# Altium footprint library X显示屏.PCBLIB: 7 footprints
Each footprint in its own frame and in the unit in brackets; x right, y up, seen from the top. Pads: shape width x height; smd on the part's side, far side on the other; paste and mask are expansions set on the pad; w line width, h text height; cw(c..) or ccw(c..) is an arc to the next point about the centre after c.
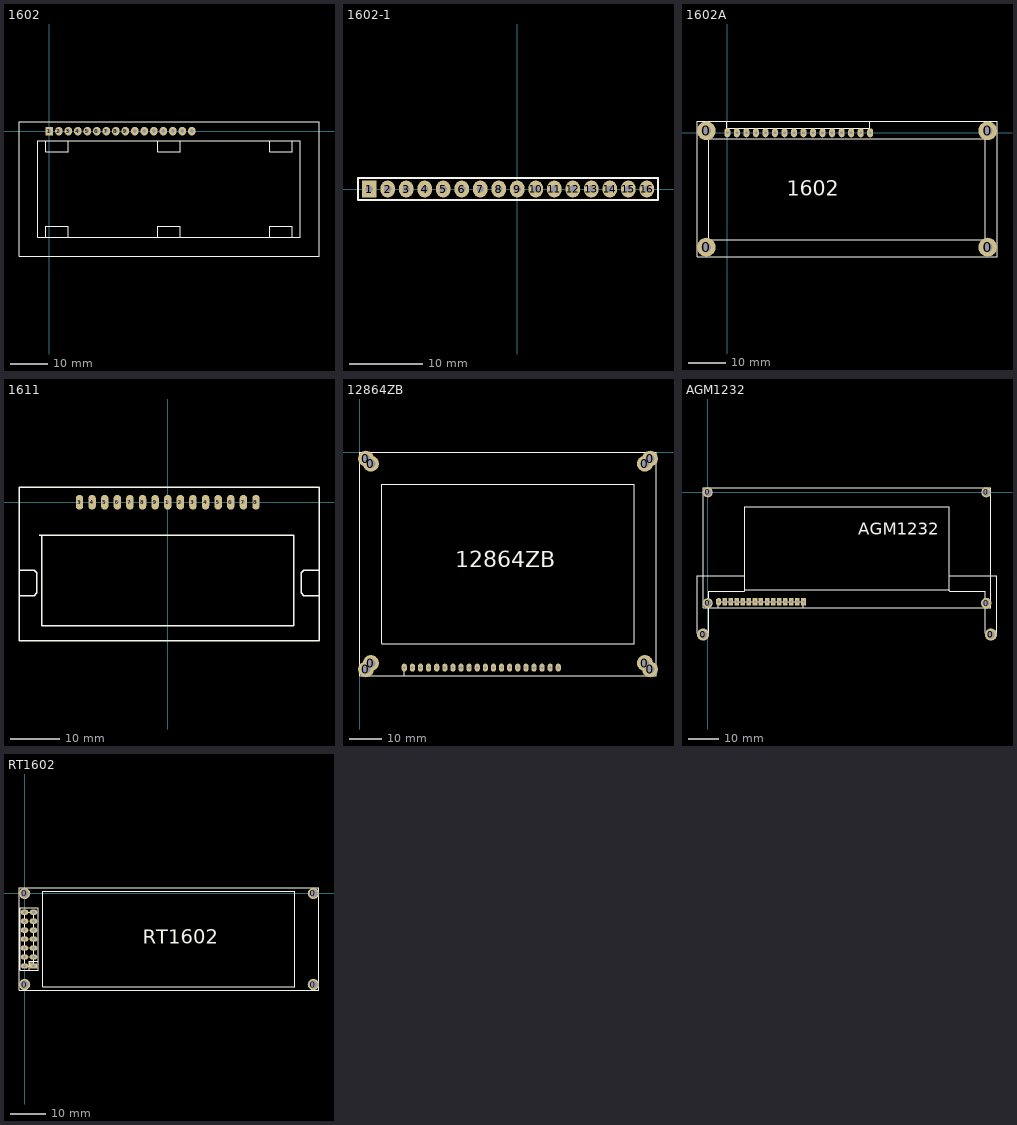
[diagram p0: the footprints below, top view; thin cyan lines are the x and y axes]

## 1602 [mm]
pads (16):
  rect 2x2.3 hole 1: 1(0,0)
  oval 2x2.3 hole 1: 2(2.54,0) 3(5.08,0) 4(7.62,0) 5(10.16,0) 6(12.7,0) 7(15.24,0) 8(17.78,0) 9(20.32,0) 10(22.86,0) 11(25.4,0) 12(27.94,0) 13(30.48,0) 14(33.02,0) 15(35.56,0) 16(38.1,0)
TopOverlay:
  lines w0.254: -1.016,-28.448 -1.016,-25.4 5.08,-25.4 5.08,-28.448 ; -1.016,-2.54 -1.016,-5.588 5.08,-5.588 5.08,-2.54 ; 28.956,-28.448 28.956,-25.4 35.052,-25.4 35.052,-28.448 ; 28.956,-2.54 28.956,-5.588 35.052,-5.588 35.052,-2.54 ; 58.928,-28.448 58.928,-25.4 65.024,-25.4 65.024,-28.448 ; 58.928,-2.54 58.928,-5.588 65.024,-5.588 65.024,-2.54 ; -8.128,-33.528 -8.128,2.54 72.136,2.54 72.136,-33.528 -8.128,-33.528 ; -3.048,-28.448 -3.048,-2.54 67.056,-2.54 67.056,-28.448 -3.048,-28.448

## 1602-1 [mm]
pads (16):
  rect 2x2.3 hole 1: 1(-20.32,0)
  oval 2x2.3 hole 1: 2(-17.78,0) 3(-15.24,0) 4(-12.7,0) 5(-10.16,0) 6(-7.62,0) 7(-5.08,0) 8(-2.54,0) 9(0,0) 10(2.54,0) 11(5.08,0) 12(7.62,0) 13(10.16,0) 14(12.7,0) 15(15.24,0) 16(17.78,0)
TopOverlay:
  lines w0.254: -21.336,-1.524 18.796,-1.524 19.304,-1.524 19.304,1.524 18.288,1.524 ; -20.828,-1.524 -21.844,-1.524 -21.844,1.524 18.796,1.524

## 1602A [mm]
pads (20):
  round 5 hole 2.5: 0(-5.588,-30.492) 0(-5.588,0.508) 0(69.412,-30.492) 0(69.412,0.508)
  oval 1.6x2.4 hole 0.762: 1(0,0) 2(2.54,0) 3(5.08,0) 4(7.62,0) 5(10.16,0) 6(12.7,0) 7(15.24,0) 8(17.78,0) 9(20.32,0) 10(22.86,0) 11(25.4,0) 12(27.94,0) 13(30.48,0) 14(33.02,0) 15(35.56,0) 16(38.1,0)
TopOverlay:
  lines w0.254: -8.088,-30.492 -5.588,-30.492 -5.588,-32.992 ; -8.088,0.508 -5.588,0.508 -5.588,3.008 ; -4.963,-15.067 -4.963,-28.467 31.887,-28.467 ; -4.963,-14.942 -4.963,-1.542 31.887,-1.542 ; -0.088,3.008 -0.088,1.208 38.012,1.208 38.012,3.008 ; 31.912,-28.467 68.762,-28.467 68.762,-15.067 ; 31.912,-1.542 68.762,-1.542 68.762,-14.942 ; -8.088,-32.992 71.912,-32.992 71.912,3.008 -8.088,3.008 -8.088,-32.992
  text "1602" at 15.9,-16.789 h4

## 1611 [mm]
pads (15):
  oval 1.5x3 hole 0.6: 1(0,0) 2(2.54,0) 3(-17.78,0) 3(5.08,0) 4(-15.24,0) 4(7.62,0) 5(-12.7,0) 5(10.16,0) 6(-10.16,0) 6(12.7,0) 7(-7.62,0) 7(15.24,0) 8(-5.08,0) 8(17.78,0) 9(-2.54,0)
TopOverlay:
  lines w0.254: -29.972,-18.796 -26.924,-18.796 -26.416,-18.288 -26.416,-14.224 -26.924,-13.716 -29.972,-13.716 ; -25.908,-6.604 25.4,-6.604 25.4,-24.892 -25.4,-24.892 -25.4,-6.604 ; 30.48,-18.796 27.432,-18.796 26.924,-18.288 26.924,-14.224 27.432,-13.716 30.48,-13.716 ; -29.972,-27.94 -29.972,3.048 30.48,3.048 30.48,-27.94 -29.972,-27.94

## 12864ZB [mm]
pads (28):
  round 5 hole 2.7: 0(2,-68) 0(2,-2) 0(3.556,-66.04) 0(3.556,-3.556) 0(89.408,-66.04) 0(89.408,-3.556) 0(91,-68) 0(91,-2)
  oval 1.6x2.5 hole 0.8: 1(62.26,-67.46) 2(59.72,-67.46) 3(57.18,-67.46) 4(54.64,-67.46) 5(52.1,-67.46) 6(49.56,-67.46) 7(47.02,-67.46) 8(44.48,-67.46) 9(41.94,-67.46) 10(39.4,-67.46) 11(36.86,-67.46) 12(34.32,-67.46) 13(31.78,-67.46) 14(29.24,-67.46) 15(26.7,-67.46) 16(24.16,-67.46) 17(21.62,-67.46) 18(19.08,-67.46) 19(16.54,-67.46) 20(14,-67.46)
TopOverlay:
  lines w0.127: 7,-60 86,-60 86,-10 7,-10 7,-59.832 7.112,-59.944 ; 14,-70 14,-67.46 ; 0,-70 93,-70 93,0 0,0 0,-70
  text "12864ZB" at 29.972,-36.068 h5

## AGM1232 [mil]
pads (21):
  round 157.48 hole 98.42: 0(-61.02,-1846.46) 0(3676.18,-1846.46)
  round 129.92 hole 90.55: 0(0,-1437.99) 0(0,0) 0(3615.16,0)
  round 137.79 hole 90.55: 0(3615.16,-1437.99)
  oct 60x100 hole 30: 1(140,-1420)
  rect 60x100 hole 30: 2(218.74,-1420) 3(297.48,-1420) 4(376.22,-1420) 5(454.96,-1420) 6(533.7,-1420) 7(612.44,-1420) 8(690,-1420) 9(770,-1420) 10(848.66,-1420) 11(927.4,-1420) 12(1006.14,-1420) 13(1084.88,-1420) 14(1163.62,-1420) 15(1242.36,-1420)
TopOverlay:
  lines w10: -61.02,-1437.99 0,-1437.99 0,-1499.02 ; -61.02,0 0,0 0,61.02 ; 135.83,-1499.02 135.83,-1420.28 1159.45,-1420.28 1238.19,-1420.28 1238.19,-1499.02 ; 482.28,-1081.69 153.54,-1081.69 -135.83,-1081.69 -135.83,-1829.72 13.78,-1829.72 13.78,-1284.45 472.44,-1284.45 482.28,-1274.61 482.28,-1266.73 ; 1809.06,-1266.73 482.28,-1266.73 ; 1809.06,-1265.75 3135.83,-1265.75 ; 1809.06,-187.99 482.28,-187.99 482.28,-727.36 482.28,-1266.73 ; 1809.06,-187.01 3135.83,-187.01 3135.83,-726.38 3135.83,-1265.75 ; 3135.83,-1080.71 3750.98,-1080.71 3750.98,-1828.74 3601.38,-1828.74 3601.38,-1284.45 3142.72,-1284.45 3135.83,-1277.56 3135.83,-1265.75 ; 3615.16,-1499.02 3615.16,-1437.99 3676.18,-1437.99 ; 3615.16,61.02 3615.16,0 3676.18,0 ; -61.02,-1499.02 -61.02,61.02 3676.18,61.02 3676.18,-1499.02 -61.02,-1499.02
  text "AGM1232" at 1954.72,-548.23 h157.48

## RT1602 [mm]
pads (18):
  round 3.2 hole 2.3: 0(0,-25.9) 0(0,0) 0(81.9,-25.9) 0(81.9,0)
  rect 2.2x1.5 hole 0.9: 1(2.515,-20.599)
  oval 2.2x1.5 hole 0.9: 2(-0.025,-20.599) 3(2.515,-18.059) 4(-0.025,-18.059) 5(2.515,-15.519) 6(-0.025,-15.519) 7(2.515,-12.979) 8(-0.025,-12.979) 9(2.515,-10.439) 10(-0.025,-10.439) 11(2.515,-7.899) 12(-0.025,-7.899) 13(2.515,-5.359) 14(-0.025,-5.359)
TopOverlay:
  lines w0.254: -1.295,-21.869 -1.295,-4.061 -1.289,-4.055 ; 1.4,-20.65 1.4,-19.675 2.55,-19.675 ; 2.55,-13.03 2.55,-20.65 0.025,-20.65 0.025,-5.35 2.55,-5.35 2.55,-12.97 ; 3.785,-21.869 3.791,-21.863 3.791,-4.055 ; -1.55,-27.475 40.95,-27.475 83.45,-27.475 83.45,-12.975 83.45,1.525 40.95,1.525 -1.55,1.525 -1.55,-12.975 -1.55,-27.475 ; 5.175,-26.475 76.675,-26.475 76.675,-12.975 76.675,0.525 40.925,0.525 5.175,0.525 5.175,-26.475
  lines w0.305: -1.295,-21.869 3.785,-21.869 ; -1.289,-4.055 3.791,-4.055 ; 1.245,-21.869 1.245,-19.329 3.785,-19.329
  text "RT1602" at 33.475,-14.275 h4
